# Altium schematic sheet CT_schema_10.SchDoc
size 274 x 160 mm
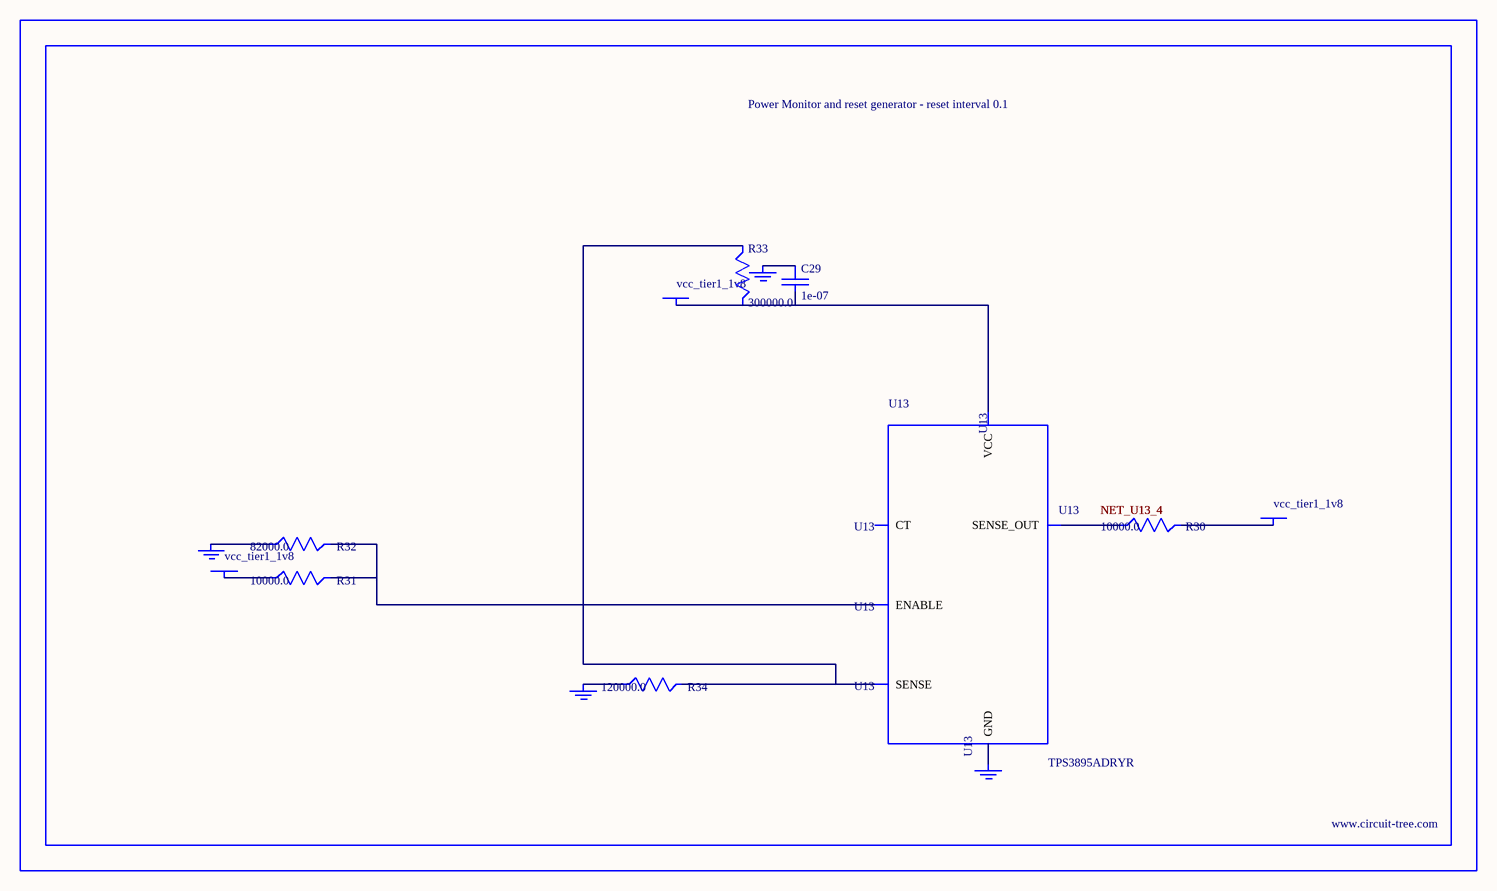
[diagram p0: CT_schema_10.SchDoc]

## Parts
BORDER9  (no value)
C29  1e-07  [C0402]
GND_INSTANCE_9_0  (no value)
GND_INSTANCE_9_1  (no value)
GND_INSTANCE_9_2  (no value)
GND_INSTANCE_9_3  (no value)
POWER_INSTANCE_9_0  vcc_tier1_1v8
POWER_INSTANCE_9_1  vcc_tier1_1v8
POWER_INSTANCE_9_2  vcc_tier1_1v8
R30  10000.0  [R0603]
R31  10000.0  [R0603]
R32  82000.0  [R0603]
R33  300000.0  [R0603]
R34  120000.0  [R0603]
U13  TPS3895ADRYR  [SON-6]

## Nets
NetC29_1: C29.1 GND_INSTANCE_9_2.0(GND)
NetC29_2: C29.2 POWER_INSTANCE_9_2.0(PWR) R33.2 U13.6(VCC)
NetGND_INSTANCE_9_0_0: GND_INSTANCE_9_0.0(GND) R32.1
NetGND_INSTANCE_9_1_0: GND_INSTANCE_9_1.0(GND) R34.1
NetGND_INSTANCE_9_3_0: GND_INSTANCE_9_3.0(GND) U13.2(GND)
NetPOWER_INSTANCE_9_0_0: POWER_INSTANCE_9_0.0(PWR) R31.1
NetPOWER_INSTANCE_9_1_0: POWER_INSTANCE_9_1.0(PWR) R30.2
NetR30_1: R30.1 U13.4(SENSE_OUT)
NetR31_2: R31.2 R32.2 U13.1(ENABLE)
NetR33_1: R33.1 R34.2 U13.3(SENSE)

Not connected (* = marked no-connect by the designer): U13 5(CT)

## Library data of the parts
BORDER9 = BORDER_PAGE9
C29 = C0402C104K3RACTU
GND_INSTANCE_9_0-GND_INSTANCE_9_3 = GND
POWER_INSTANCE_9_0-POWER_INSTANCE_9_2 = PWR
R30 R31 = RC0603JR-0710KL
R32 = RC0603JR-0782KL
R33 = RC0603JR-07300KL
R34 = RC0603JR-07120KL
